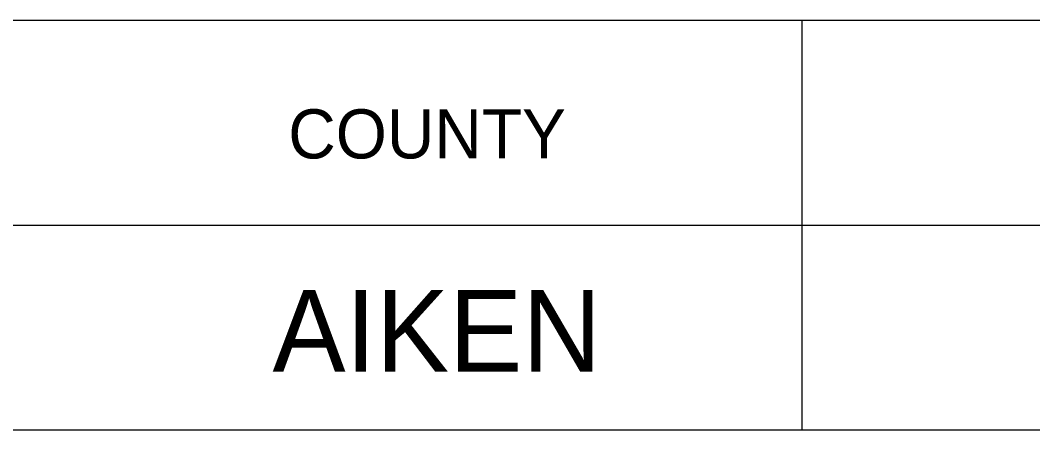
# Model space of a CAD drawing. Extents: x 1000 to 1162, y 999 to 8520.
# Drawn here: x 1139.23 to 1145.41, y 7195.05 to 7197.55 of the extents above; entities that cross this region are included whole.
import ezdxf

# ---------------------------------------------------------------- set-up
doc = ezdxf.new("R2010")
doc.units = 0
doc.layers.add('Level 20', color=7, linetype='Continuous')
doc.layers.add('Level 3', color=7, linetype='Continuous')

msp = doc.modelspace()

# ---------------------------------------------------------------- linework, layer by layer
at = {"layer": 'Level 3'}
for p, q in [((1133.055, 7197.5458), (1161.555, 7197.5458)), ((1133.055, 7197.5458), (1161.555, 7197.5458)), ((1133.055, 7197.5458), (1161.555, 7197.5458)), ((1133.055, 7197.5458), (1161.555, 7197.5458)), ((1133.055, 7197.5458), (1161.555, 7197.5458)), ((1133.055, 7197.5458), (1161.555, 7197.5458)), ((1133.055, 7197.5458), (1161.555, 7197.5458)), ((1133.055, 7197.5458), (1161.555, 7197.5458)), ((1133.055, 7197.5458), (1161.555, 7197.5458)), ((1133.055, 7197.5458), (1161.555, 7197.5458)), ((1133.055, 7197.5458), (1161.555, 7197.5458)), ((1133.055, 7197.5458), (1161.555, 7197.5458)), ((1133.055, 7197.5458), (1161.555, 7197.5458)), ((1133.055, 7197.5458), (1161.555, 7197.5458)), ((1133.055, 7197.5458), (1161.555, 7197.5458)), ((1133.055, 7197.5458), (1161.555, 7197.5458)), ((1133.055, 7197.5458), (1161.555, 7197.5458)), ((1133.055, 7197.5458), (1161.555, 7197.5458)), ((1133.055, 7197.5458), (1161.555, 7197.5458)), ((1133.055, 7197.5458), (1161.555, 7197.5458)), ((1133.055, 7197.5458), (1161.555, 7197.5458)), ((1133.055, 7197.5458), (1161.555, 7197.5458)), ((1133.055, 7197.5458), (1161.555, 7197.5458)), ((1133.055, 7197.5458), (1161.555, 7197.5458)), ((1133.055, 7197.5458), (1161.555, 7197.5458)), ((1133.055, 7197.5458), (1161.555, 7197.5458)), ((1133.055, 7197.5458), (1161.555, 7197.5458)), ((1133.055, 7197.5458), (1161.555, 7197.5458)), ((1133.055, 7197.5458), (1161.555, 7197.5458)), ((1133.055, 7197.5458), (1161.555, 7197.5458)), ((1133.055, 7197.5458), (1161.555, 7197.5458)), ((1133.055, 7197.5458), (1161.555, 7197.5458)), ((1133.055, 7197.5458), (1161.555, 7197.5458)), ((1133.055, 7197.5458), (1161.555, 7197.5458)), ((1133.055, 7197.5458), (1161.555, 7197.5458)), ((1133.055, 7197.5458), (1161.555, 7197.5458)), ((1133.055, 7197.5458), (1161.555, 7197.5458)), ((1133.055, 7197.5458), (1161.555, 7197.5458)), ((1133.055, 7197.5458), (1161.555, 7197.5458)), ((1133.055, 7197.5458), (1161.555, 7197.5458)), ((1133.055, 7197.5458), (1161.555, 7197.5458)), ((1133.055, 7197.5458), (1161.555, 7197.5458)), ((1133.055, 7197.5458), (1161.555, 7197.5458)), ((1133.055, 7197.5458), (1161.555, 7197.5458)), ((1133.055, 7197.5458), (1161.555, 7197.5458)), ((1133.055, 7197.5458), (1161.555, 7197.5458)), ((1133.055, 7197.5458), (1161.555, 7197.5458)), ((1133.055, 7197.5458), (1161.555, 7197.5458)), ((1133.055, 7197.5458), (1161.555, 7197.5458)), ((1133.055, 7197.5458), (1161.555, 7197.5458)), ((1133.055, 7197.5458), (1161.555, 7197.5458)), ((1133.055, 7197.5458), (1161.555, 7197.5458)), ((1143.9997, 7197.5458), (1143.9997, 7195.0458)), ((1143.9997, 7197.5458), (1143.9997, 7195.0458)), ((1143.9997, 7197.5458), (1143.9997, 7195.0458)), ((1143.9997, 7197.5458), (1143.9997, 7195.0458)), ((1143.9997, 7197.5458), (1143.9997, 7195.0458)), ((1143.9997, 7197.5458), (1143.9997, 7195.0458)), ((1143.9997, 7197.5458), (1143.9997, 7195.0458)), ((1143.9997, 7197.5458), (1143.9997, 7195.0458)), ((1143.9997, 7197.5458), (1143.9997, 7195.0458)), ((1143.9997, 7197.5458), (1143.9997, 7195.0458)), ((1143.9997, 7197.5458), (1143.9997, 7195.0458)), ((1143.9997, 7197.5458), (1143.9997, 7195.0458)), ((1143.9997, 7197.5458), (1143.9997, 7195.0458)), ((1143.9997, 7197.5458), (1143.9997, 7195.0458)), ((1143.9997, 7197.5458), (1143.9997, 7195.0458)), ((1143.9997, 7197.5458), (1143.9997, 7195.0458)), ((1143.9997, 7197.5458), (1143.9997, 7195.0458)), ((1143.9997, 7197.5458), (1143.9997, 7195.0458)), ((1143.9997, 7197.5458), (1143.9997, 7195.0458)), ((1143.9997, 7197.5458), (1143.9997, 7195.0458)), ((1143.9997, 7197.5458), (1143.9997, 7195.0458)), ((1143.9997, 7197.5458), (1143.9997, 7195.0458)), ((1143.9997, 7197.5458), (1143.9997, 7195.0458)), ((1143.9997, 7197.5458), (1143.9997, 7195.0458)), ((1143.9997, 7197.5458), (1143.9997, 7195.0458)), ((1143.9997, 7197.5458), (1143.9997, 7195.0458)), ((1143.9997, 7197.5458), (1143.9997, 7195.0458)), ((1143.9997, 7197.5458), (1143.9997, 7195.0458)), ((1143.9997, 7197.5458), (1143.9997, 7195.0458)), ((1143.9997, 7197.5458), (1143.9997, 7195.0458)), ((1143.9997, 7197.5458), (1143.9997, 7195.0458)), ((1143.9997, 7197.5458), (1143.9997, 7195.0458)), ((1143.9997, 7197.5458), (1143.9997, 7195.0458)), ((1143.9997, 7197.5458), (1143.9997, 7195.0458)), ((1143.9997, 7197.5458), (1143.9997, 7195.0458)), ((1143.9997, 7197.5458), (1143.9997, 7195.0458)), ((1143.9997, 7197.5458), (1143.9997, 7195.0458)), ((1143.9997, 7197.5458), (1143.9997, 7195.0458)), ((1143.9997, 7197.5458), (1143.9997, 7195.0458)), ((1143.9997, 7197.5458), (1143.9997, 7195.0458)), ((1143.9997, 7197.5458), (1143.9997, 7195.0458)), ((1143.9997, 7197.5458), (1143.9997, 7195.0458)), ((1143.9997, 7197.5458), (1143.9997, 7195.0458)), ((1143.9997, 7197.5458), (1143.9997, 7195.0458)), ((1143.9997, 7197.5458), (1143.9997, 7195.0458)), ((1143.9997, 7197.5458), (1143.9997, 7195.0458)), ((1143.9997, 7197.5458), (1143.9997, 7195.0458)), ((1143.9997, 7197.5458), (1143.9997, 7195.0458)), ((1143.9997, 7197.5458), (1143.9997, 7195.0458)), ((1143.9997, 7197.5458), (1143.9997, 7195.0458)), ((1143.9997, 7197.5458), (1143.9997, 7195.0458)), ((1143.9997, 7197.5458), (1143.9997, 7195.0458)), ((1133.055, 7196.2958), (1161.555, 7196.2958)), ((1133.055, 7196.2958), (1161.555, 7196.2958)), ((1133.055, 7196.2958), (1161.555, 7196.2958)), ((1133.055, 7196.2958), (1161.555, 7196.2958)), ((1133.055, 7196.2958), (1161.555, 7196.2958)), ((1133.055, 7196.2958), (1161.555, 7196.2958)), ((1133.055, 7196.2958), (1161.555, 7196.2958)), ((1133.055, 7196.2958), (1161.555, 7196.2958)), ((1133.055, 7196.2958), (1161.555, 7196.2958)), ((1133.055, 7196.2958), (1161.555, 7196.2958)), ((1133.055, 7196.2958), (1161.555, 7196.2958)), ((1133.055, 7196.2958), (1161.555, 7196.2958)), ((1133.055, 7196.2958), (1161.555, 7196.2958)), ((1133.055, 7196.2958), (1161.555, 7196.2958)), ((1133.055, 7196.2958), (1161.555, 7196.2958)), ((1133.055, 7196.2958), (1161.555, 7196.2958)), ((1133.055, 7196.2958), (1161.555, 7196.2958)), ((1133.055, 7196.2958), (1161.555, 7196.2958)), ((1133.055, 7196.2958), (1161.555, 7196.2958)), ((1133.055, 7196.2958), (1161.555, 7196.2958)), ((1133.055, 7196.2958), (1161.555, 7196.2958)), ((1133.055, 7196.2958), (1161.555, 7196.2958)), ((1133.055, 7196.2958), (1161.555, 7196.2958)), ((1133.055, 7196.2958), (1161.555, 7196.2958)), ((1133.055, 7196.2958), (1161.555, 7196.2958)), ((1133.055, 7196.2958), (1161.555, 7196.2958)), ((1133.055, 7196.2958), (1161.555, 7196.2958)), ((1133.055, 7196.2958), (1161.555, 7196.2958)), ((1133.055, 7196.2958), (1161.555, 7196.2958)), ((1133.055, 7196.2958), (1161.555, 7196.2958)), ((1133.055, 7196.2958), (1161.555, 7196.2958)), ((1133.055, 7196.2958), (1161.555, 7196.2958)), ((1133.055, 7196.2958), (1161.555, 7196.2958)), ((1133.055, 7196.2958), (1161.555, 7196.2958)), ((1133.055, 7196.2958), (1161.555, 7196.2958)), ((1133.055, 7196.2958), (1161.555, 7196.2958)), ((1133.055, 7196.2958), (1161.555, 7196.2958)), ((1133.055, 7196.2958), (1161.555, 7196.2958)), ((1133.055, 7196.2958), (1161.555, 7196.2958)), ((1133.055, 7196.2958), (1161.555, 7196.2958)), ((1133.055, 7196.2958), (1161.555, 7196.2958)), ((1133.055, 7196.2958), (1161.555, 7196.2958)), ((1133.055, 7196.2958), (1161.555, 7196.2958)), ((1133.055, 7196.2958), (1161.555, 7196.2958)), ((1133.055, 7196.2958), (1161.555, 7196.2958)), ((1133.055, 7196.2958), (1161.555, 7196.2958)), ((1133.055, 7196.2958), (1161.555, 7196.2958)), ((1133.055, 7196.2958), (1161.555, 7196.2958)), ((1133.055, 7196.2958), (1161.555, 7196.2958)), ((1133.055, 7196.2958), (1161.555, 7196.2958)), ((1133.055, 7196.2958), (1161.555, 7196.2958)), ((1133.055, 7196.2958), (1161.555, 7196.2958)), ((1133.055, 7195.0458), (1161.555, 7195.0458)), ((1133.055, 7195.0458), (1161.555, 7195.0458)), ((1133.055, 7195.0458), (1161.555, 7195.0458)), ((1133.055, 7195.0458), (1161.555, 7195.0458)), ((1133.055, 7195.0458), (1161.555, 7195.0458)), ((1133.055, 7195.0458), (1161.555, 7195.0458)), ((1133.055, 7195.0458), (1161.555, 7195.0458)), ((1133.055, 7195.0458), (1161.555, 7195.0458)), ((1133.055, 7195.0458), (1161.555, 7195.0458)), ((1133.055, 7195.0458), (1161.555, 7195.0458)), ((1133.055, 7195.0458), (1161.555, 7195.0458)), ((1133.055, 7195.0458), (1161.555, 7195.0458)), ((1133.055, 7195.0458), (1161.555, 7195.0458)), ((1133.055, 7195.0458), (1161.555, 7195.0458)), ((1133.055, 7195.0458), (1161.555, 7195.0458)), ((1133.055, 7195.0458), (1161.555, 7195.0458)), ((1133.055, 7195.0458), (1161.555, 7195.0458)), ((1133.055, 7195.0458), (1161.555, 7195.0458)), ((1133.055, 7195.0458), (1161.555, 7195.0458)), ((1133.055, 7195.0458), (1161.555, 7195.0458)), ((1133.055, 7195.0458), (1161.555, 7195.0458)), ((1133.055, 7195.0458), (1161.555, 7195.0458)), ((1133.055, 7195.0458), (1161.555, 7195.0458)), ((1133.055, 7195.0458), (1161.555, 7195.0458)), ((1133.055, 7195.0458), (1161.555, 7195.0458)), ((1133.055, 7195.0458), (1161.555, 7195.0458)), ((1133.055, 7195.0458), (1161.555, 7195.0458)), ((1133.055, 7195.0458), (1161.555, 7195.0458)), ((1133.055, 7195.0458), (1161.555, 7195.0458)), ((1133.055, 7195.0458), (1161.555, 7195.0458)), ((1133.055, 7195.0458), (1161.555, 7195.0458)), ((1133.055, 7195.0458), (1161.555, 7195.0458)), ((1133.055, 7195.0458), (1161.555, 7195.0458)), ((1133.055, 7195.0458), (1161.555, 7195.0458)), ((1133.055, 7195.0458), (1161.555, 7195.0458)), ((1133.055, 7195.0458), (1161.555, 7195.0458)), ((1133.055, 7195.0458), (1161.555, 7195.0458)), ((1133.055, 7195.0458), (1161.555, 7195.0458)), ((1133.055, 7195.0458), (1161.555, 7195.0458)), ((1133.055, 7195.0458), (1161.555, 7195.0458)), ((1133.055, 7195.0458), (1161.555, 7195.0458)), ((1133.055, 7195.0458), (1161.555, 7195.0458)), ((1133.055, 7195.0458), (1161.555, 7195.0458)), ((1133.055, 7195.0458), (1161.555, 7195.0458)), ((1133.055, 7195.0458), (1161.555, 7195.0458)), ((1133.055, 7195.0458), (1161.555, 7195.0458)), ((1133.055, 7195.0458), (1161.555, 7195.0458)), ((1133.055, 7195.0458), (1161.555, 7195.0458)), ((1133.055, 7195.0458), (1161.555, 7195.0458)), ((1133.055, 7195.0458), (1161.555, 7195.0458)), ((1133.055, 7195.0458), (1161.555, 7195.0458)), ((1133.055, 7195.0458), (1161.555, 7195.0458))]:
    msp.add_line(p, q, dxfattribs=at)

# ---------------------------------------------------------------- texts
at = {"layer": 'Level 20'}
msp.add_text('AIKEN', height=0.5, dxfattribs=at).set_placement((1140.7706, 7195.4))
at = {"layer": 'Level 3'}
msp.add_text('COUNTY', height=0.3, dxfattribs=at).set_placement((1140.8665, 7196.7021))
msp.add_text('COUNTY', height=0.3, dxfattribs=at).set_placement((1140.8665, 7196.7021))
msp.add_text('COUNTY', height=0.3, dxfattribs=at).set_placement((1140.8665, 7196.7021))
msp.add_text('COUNTY', height=0.3, dxfattribs=at).set_placement((1140.8665, 7196.7021))
msp.add_text('COUNTY', height=0.3, dxfattribs=at).set_placement((1140.8665, 7196.7021))
msp.add_text('COUNTY', height=0.3, dxfattribs=at).set_placement((1140.8665, 7196.7021))
msp.add_text('COUNTY', height=0.3, dxfattribs=at).set_placement((1140.8665, 7196.7021))
msp.add_text('COUNTY', height=0.3, dxfattribs=at).set_placement((1140.8665, 7196.7021))
msp.add_text('COUNTY', height=0.3, dxfattribs=at).set_placement((1140.8665, 7196.7021))
msp.add_text('COUNTY', height=0.3, dxfattribs=at).set_placement((1140.8665, 7196.7021))
msp.add_text('COUNTY', height=0.3, dxfattribs=at).set_placement((1140.8665, 7196.7021))
msp.add_text('COUNTY', height=0.3, dxfattribs=at).set_placement((1140.8665, 7196.7021))
msp.add_text('COUNTY', height=0.3, dxfattribs=at).set_placement((1140.8665, 7196.7021))
msp.add_text('COUNTY', height=0.3, dxfattribs=at).set_placement((1140.8665, 7196.7021))
msp.add_text('COUNTY', height=0.3, dxfattribs=at).set_placement((1140.8665, 7196.7021))
msp.add_text('COUNTY', height=0.3, dxfattribs=at).set_placement((1140.8665, 7196.7021))
msp.add_text('COUNTY', height=0.3, dxfattribs=at).set_placement((1140.8665, 7196.7021))
msp.add_text('COUNTY', height=0.3, dxfattribs=at).set_placement((1140.8665, 7196.7021))
msp.add_text('COUNTY', height=0.3, dxfattribs=at).set_placement((1140.8665, 7196.7021))
msp.add_text('COUNTY', height=0.3, dxfattribs=at).set_placement((1140.8665, 7196.7021))
msp.add_text('COUNTY', height=0.3, dxfattribs=at).set_placement((1140.8665, 7196.7021))
msp.add_text('COUNTY', height=0.3, dxfattribs=at).set_placement((1140.8665, 7196.7021))
msp.add_text('COUNTY', height=0.3, dxfattribs=at).set_placement((1140.8665, 7196.7021))
msp.add_text('COUNTY', height=0.3, dxfattribs=at).set_placement((1140.8665, 7196.7021))
msp.add_text('COUNTY', height=0.3, dxfattribs=at).set_placement((1140.8665, 7196.7021))
msp.add_text('COUNTY', height=0.3, dxfattribs=at).set_placement((1140.8665, 7196.7021))
msp.add_text('COUNTY', height=0.3, dxfattribs=at).set_placement((1140.8665, 7196.7021))
msp.add_text('COUNTY', height=0.3, dxfattribs=at).set_placement((1140.8665, 7196.7021))
msp.add_text('COUNTY', height=0.3, dxfattribs=at).set_placement((1140.8665, 7196.7021))
msp.add_text('COUNTY', height=0.3, dxfattribs=at).set_placement((1140.8665, 7196.7021))
msp.add_text('COUNTY', height=0.3, dxfattribs=at).set_placement((1140.8665, 7196.7021))
msp.add_text('COUNTY', height=0.3, dxfattribs=at).set_placement((1140.8665, 7196.7021))
msp.add_text('COUNTY', height=0.3, dxfattribs=at).set_placement((1140.8665, 7196.7021))
msp.add_text('COUNTY', height=0.3, dxfattribs=at).set_placement((1140.8665, 7196.7021))
msp.add_text('COUNTY', height=0.3, dxfattribs=at).set_placement((1140.8665, 7196.7021))
msp.add_text('COUNTY', height=0.3, dxfattribs=at).set_placement((1140.8665, 7196.7021))
msp.add_text('COUNTY', height=0.3, dxfattribs=at).set_placement((1140.8665, 7196.7021))
msp.add_text('COUNTY', height=0.3, dxfattribs=at).set_placement((1140.8665, 7196.7021))
msp.add_text('COUNTY', height=0.3, dxfattribs=at).set_placement((1140.8665, 7196.7021))
msp.add_text('COUNTY', height=0.3, dxfattribs=at).set_placement((1140.8665, 7196.7021))
msp.add_text('COUNTY', height=0.3, dxfattribs=at).set_placement((1140.8665, 7196.7021))
msp.add_text('COUNTY', height=0.3, dxfattribs=at).set_placement((1140.8665, 7196.7021))
msp.add_text('COUNTY', height=0.3, dxfattribs=at).set_placement((1140.8665, 7196.7021))
msp.add_text('COUNTY', height=0.3, dxfattribs=at).set_placement((1140.8665, 7196.7021))
msp.add_text('COUNTY', height=0.3, dxfattribs=at).set_placement((1140.8665, 7196.7021))
msp.add_text('COUNTY', height=0.3, dxfattribs=at).set_placement((1140.8665, 7196.7021))
msp.add_text('COUNTY', height=0.3, dxfattribs=at).set_placement((1140.8665, 7196.7021))
msp.add_text('COUNTY', height=0.3, dxfattribs=at).set_placement((1140.8665, 7196.7021))
msp.add_text('COUNTY', height=0.3, dxfattribs=at).set_placement((1140.8665, 7196.7021))
msp.add_text('COUNTY', height=0.3, dxfattribs=at).set_placement((1140.8665, 7196.7021))
msp.add_text('COUNTY', height=0.3, dxfattribs=at).set_placement((1140.8665, 7196.7021))
msp.add_text('COUNTY', height=0.3, dxfattribs=at).set_placement((1140.8665, 7196.7021))

doc.saveas('drawing.dxf')
